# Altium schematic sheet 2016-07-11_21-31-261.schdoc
size 521 x 193 mm; SheetNumber: 1; SheetTotal: 1
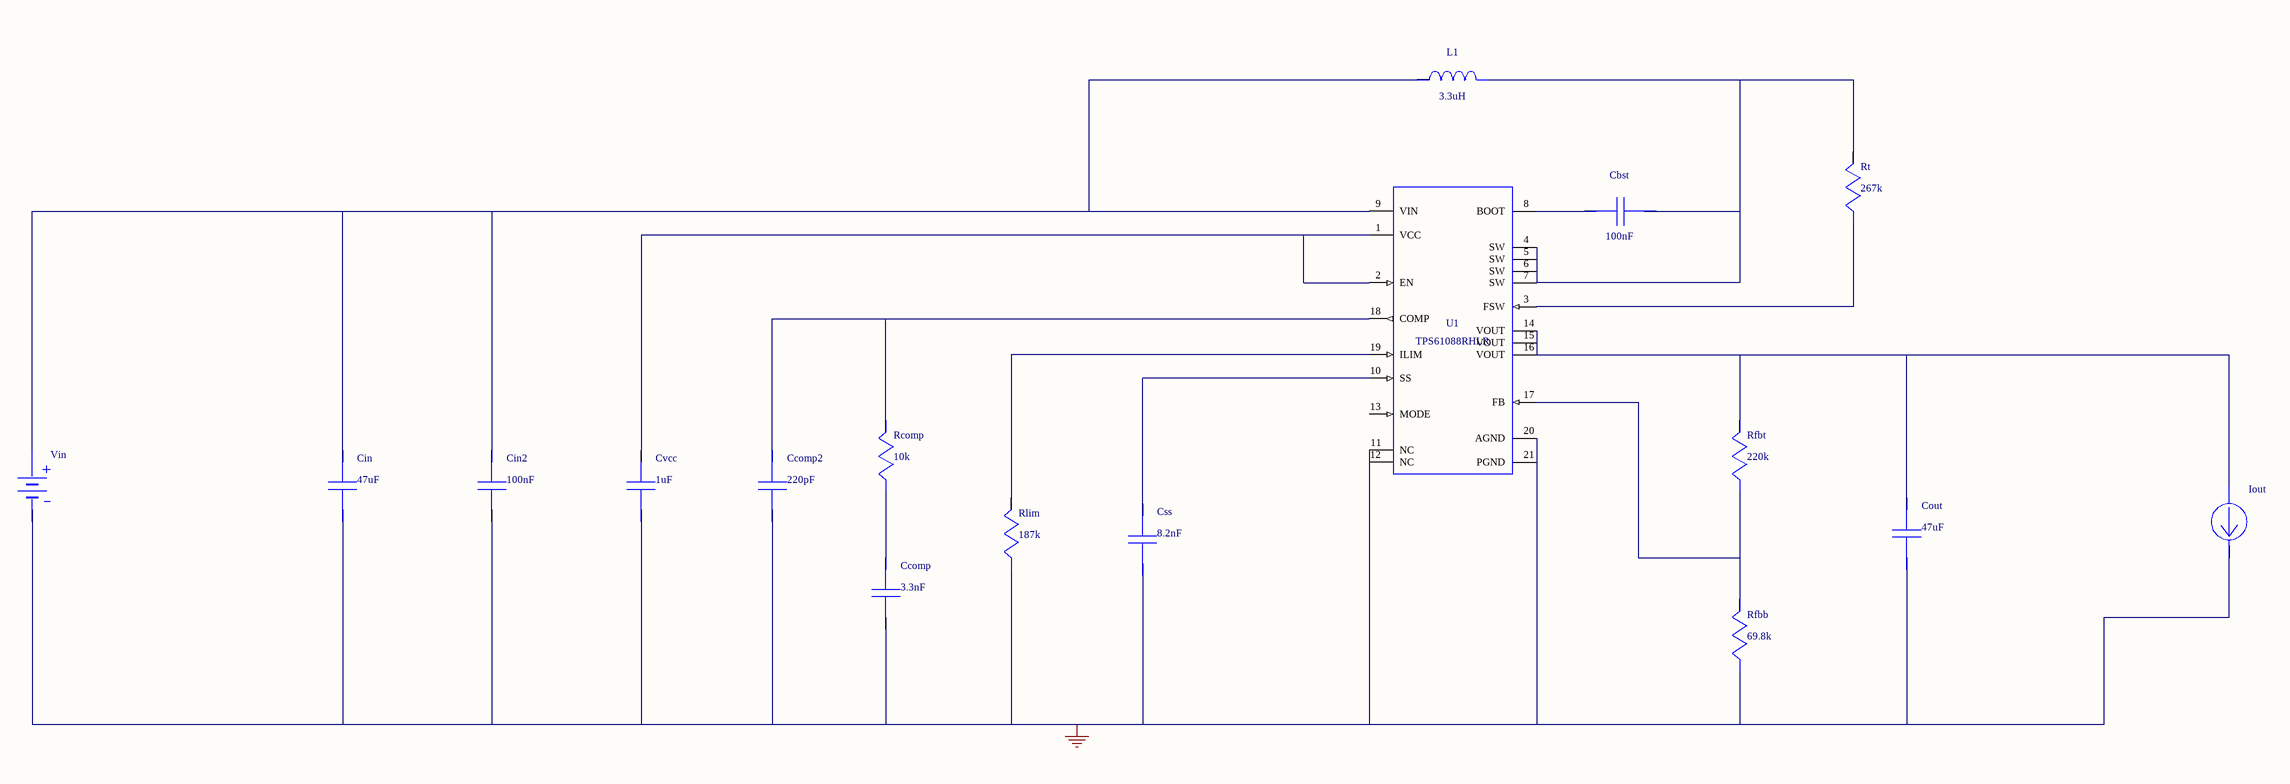
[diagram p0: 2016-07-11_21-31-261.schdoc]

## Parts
Cbst  value 100nF  (hidden comment: 08053C104KAT2A)
Ccomp  value 3.3nF  (hidden comment: GRM033R71C332KA88D)
Ccomp2  value 220pF  (hidden comment: GRM033R71C221KA01D)
Cin  value 47uF  (hidden comment: GRM31CR61A476KE15L)
Cin2  value 100nF  (hidden comment: GRM155R60J104KA01D)
Cout  value 47uF  (hidden comment: GRM31CR61A476KE15L)
Css  value 8.2nF  (hidden comment: GRM155R71C822KA01D)
Cvcc  value 1uF  (hidden comment: GRM188R61A105KA61D)
Iout  WB_CURRENT_LOAD  (value not drawn)
L1  value 3.3uH  (hidden comment: VLP8040T-3R3N)
Rcomp  value 10k  (hidden comment: CRCW040210K0FKED)
Rfbb  value 69.8k  (hidden comment: CRCW040269K8FKED)
Rfbt  value 220k  (hidden comment: RC0603FR-07220KL)
Rlim  value 187k  (hidden comment: CRCW0402187KFKED)
Rt  value 267k  (hidden comment: CRCW0402267KFKED)
U1  TPS61088RHLR
Vin  WB_BATTERY  (value not drawn)

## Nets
0: Ccomp.2 Ccomp2.2 Cin.2 Cin2.2 Cout.2 Css.2 Cvcc.2 Iout.2(-) Rfbb.2 Rlim.2 U1.11(NC) U1.12(NC) U1.20(AGND) U1.21(PGND) Vin.2(-)
NetCbst_1: Cbst.1 U1.8(BOOT)
NetCbst_2: Cbst.2 L1.2 Rt.1 U1.4(SW) U1.5(SW) U1.6(SW) U1.7(SW)
NetCcomp2_1: Ccomp2.1 Rcomp.1 U1.18(COMP)
NetCcomp_1: Ccomp.1 Rcomp.2
NetCin_1: Cin.1 Cin2.1 L1.1 U1.9(VIN) Vin.1(+)
NetCout_1: Cout.1 Iout.1(+) Rfbt.1 U1.14(VOUT) U1.15(VOUT) U1.16(VOUT)
NetCss_1: Css.1 U1.10(SS)
NetCvcc_1: Cvcc.1 U1.1(VCC) U1.2(EN)
NetRfbb_1: Rfbb.1 Rfbt.2 U1.17(FB)
NetRlim_1: Rlim.1 U1.19(ILIM)
NetRt_2: Rt.2 U1.3(FSW)

Not connected (* = marked no-connect by the designer): U1 13(MODE)

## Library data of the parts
Cbst = 08053C104KAT2A: Manufacturer Name: AVX
Ccomp = GRM033R71C332KA88D: GRM033R71C332KA8; Manufacturer Name: MuRata
Ccomp2 = GRM033R71C221KA01D: GRM033R71C221KA0; Manufacturer Name: MuRata
Cin Cout = GRM31CR61A476KE15L: GRM31CR61A476KE1; Manufacturer Name: MuRata
Cin2 = GRM155R60J104KA01D: GRM155R60J104KA0; Manufacturer Name: MuRata
Css = GRM155R71C822KA01D: GRM155R71C822KA0; Manufacturer Name: MuRata
Cvcc = GRM188R61A105KA61D: GRM188R61A105KA6; Manufacturer Name: MuRata
L1 = VLP8040T-3R3N: Unknown; Manufacturer Name: TDK
Rcomp = CRCW040210K0FKED: Manufacturer Name: Vishay-Dale
Rfbb = CRCW040269K8FKED: Manufacturer Name: Vishay-Dale
Rfbt = RC0603FR-07220KL: Manufacturer Name: Yageo America
Rlim = CRCW0402187KFKED: Manufacturer Name: Vishay-Dale
Rt = CRCW0402267KFKED: Manufacturer Name: Vishay-Dale
U1 = TPS61088RHLR: Manufacturer Name: Texas Instruments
